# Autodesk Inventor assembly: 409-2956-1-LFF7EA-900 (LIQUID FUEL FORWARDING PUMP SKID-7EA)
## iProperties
Created: 2010-09
Part Number: 409-2956-1-LFF7EA-900 (LIQUID FUEL FORWARDING PUMP SKID-7EA)
Document SubType Name: Assembly
Designer: S. Boerckel
Mass: 2.7134e+06 g
Surface Area: 791272 cm^2
Volume: 404258 cm^3
Density: 6.71204 g/cm^3
Description: CONTROLS & ELECTRICAL
Material: ASSEMBLY
SMR: =<MATERIAL>
Author: S. Boerckel
Revision Number: 0
